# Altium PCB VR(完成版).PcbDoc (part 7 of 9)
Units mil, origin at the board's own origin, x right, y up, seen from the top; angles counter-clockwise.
Board outline 2839.68 x 2020.7 mil, 6 copper layers (TOP, GND02, SIN03, SIN04, PWR05, BOTTOM); 494 components, 404 nets, 7124 pads, 1123 vias.
Unrouted connection lines stored in the file: 10.
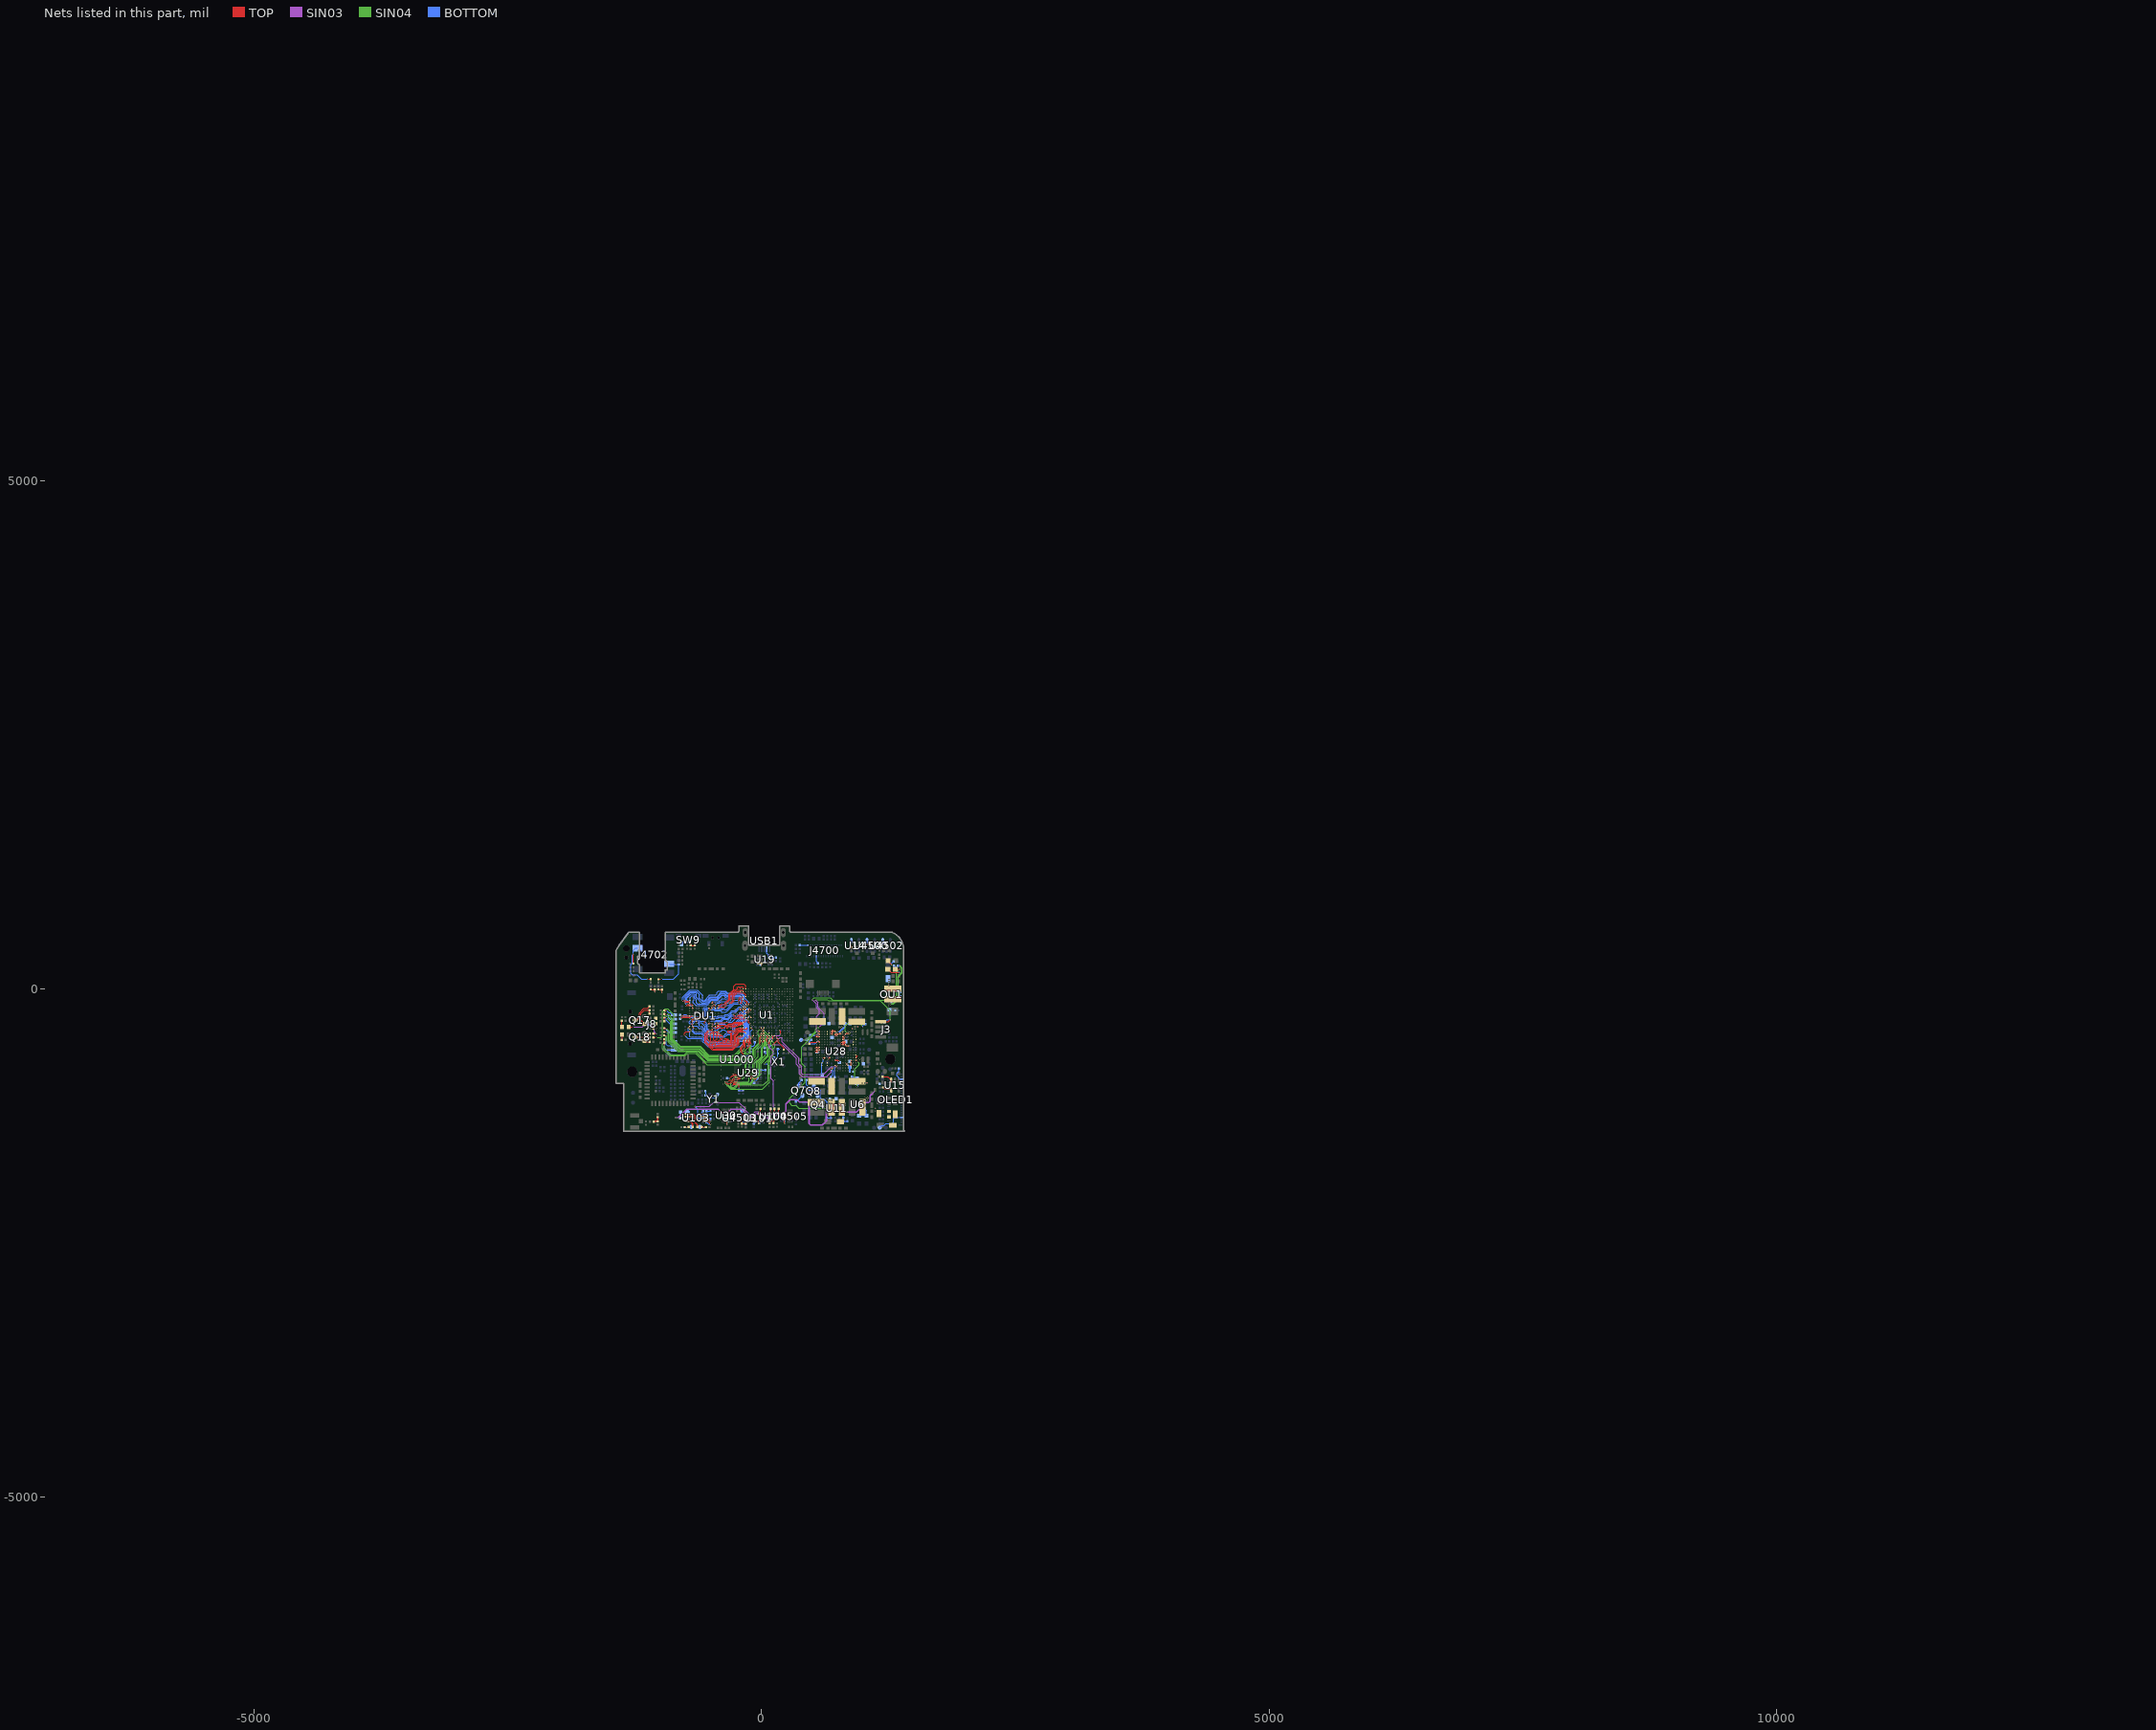
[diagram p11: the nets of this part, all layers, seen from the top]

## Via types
v1: diameter 14, hole 8, TOP to BOTTOM, tented both sides, 707 vias
v2: diameter 16, hole 10, TOP to BOTTOM, tented both sides, 275 vias
v3: diameter 16, hole 8, TOP to BOTTOM, tented both sides, 134 vias
v4: diameter 8, hole 8, TOP to BOTTOM, tented both sides, 3 vias
v5: diameter 10, hole 10, TOP to BOTTOM, tented both sides, 2 vias
v6: diameter 14, hole 8, TOP to BOTTOM, tented top, 1 vias
v7: diameter 14, hole 10, TOP to BOTTOM, tented both sides, 1 vias

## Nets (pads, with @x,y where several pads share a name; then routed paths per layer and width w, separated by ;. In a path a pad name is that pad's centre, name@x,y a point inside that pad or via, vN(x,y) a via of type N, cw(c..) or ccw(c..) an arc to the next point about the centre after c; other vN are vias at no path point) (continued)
N17861480: C240.1 R186.2 Y1.1 | length 203.2
  BOTTOM w5: C240.1@-551,-1006 -547.62,-1009.38 R186.2@-547.62,-1048.69 -522.31,-1074 -440,-1074 -430.01,-1064.01 Y1.1@-430.01,-1037.17
N20258136: D3.1 R18.1 | length 94.7
  TOP w5: D3.1@1246.33,276.14 v1(1283.73,238.74) v1@1283.73,238.14
  BOTTOM w5: v1(1283.73,238.74) 1283.73,251.71 R18.1@1303.73,271.71
N20498419: C8.1 U1.Y15 | length 140.8
  TOP w5: U1.Y15@153.54,-486.23 166,-498.69 166,-524 222,-580 C8.1@222,-598.64
N20508570: C31.2 R5.1 X1.3 | length 154
  BOTTOM w5: X1.3@117.7,-681.86 151.33,-681.86 162.19,-671 C31.2@162.19,-634.86 ; C31.2@163,-634.86 R5.1@163,-593 v1(190,-593)
N21025268: DR5.1 U1.T5 | length 279.4
  TOP w4: U1.T5@-102.36,-383.86 v1(-89.56,-396.65)
  BOTTOM w5: v1@-88.69,-397.63 -107.08,-416.02 -107.08,-503.08 -121,-517 -121,-552 -108,-565 -78,-565 -63.98,-550.98 DR5.1@-63.98,-525.69
N21042222: C134.2 R88.2 R89.1 | length 83.1
  BOTTOM w5: R88.2@766.81,-1305.24 R88.2@766.81,-1303.69
  BOTTOM w10: R88.2@766.81,-1303.69 C134.2@848.41,-1303.69
N21042253: D12.1 L9.2 U11.1
  other v2: 766.73,-1150.86 825.73,-1146.86 767.73,-1127.86 825.73,-1126.86
N21042265: R85.1 R89.2 U11.3 | length 510.1
  SIN03 w15: v1(844,-1213) 936,-1213 1028,-1121 1054,-1121 1070,-1105 1070,-1054.59 v2(1119.73,-1004.86) v2(1119.73,-984.86)
  BOTTOM w5: U11.3@803.25,-1212.26 U11.3@807.61,-1212.26
  BOTTOM w10: R89.2@807.61,-1269.86 U11.3@807.61,-1212.26 ; v1@843.26,-1212.26 v1(844,-1213)
  BOTTOM w15: U11.3@807.61,-1212.26 v1@843.26,-1212.26
N21069307: D37.1 R136.1 R140.2 USB1.4 | length 160.2
  BOTTOM w5: USB1.4@54.32,391.45 54.32,353 70.73,336.59 R140.2@70.73,309.27 ; R140.2@70.73,309.14 R140.2@70.73,309.27 ; R136.1@141.73,309.14 70.86,309.14 R140.2@70.73,309.27
N21069496: R137.2 U19.3 | length 41.8
  TOP w5: U19.3@-11.45,250.74 6.13,250.74 7.73,249.14 v1@7.73,227.14
  other v1: 7.73,233.14
N21107518: C176.2 D14.1 J8.4 R121.2
  other v1: -1029.27,-398.86 -1030.27,-378.86
N21149587: OU1.3 R22.2 R23.1 | length 119.9
  BOTTOM w5: OU1.3@1318.13,3.35 1318.13,-26.26 1324.11,-32.24 R22.2@1365.73,-32.24 R23.1@1365.73,-72.48
N21149589: OD1.1 OL1.2 OU1.1
  other v1: 1256,34.14 1256,55.14 1256,74 1257,93.14
N21179643: C206.1 C208.1 C212.2 R152.2 U28.C3 U28.D3 U28.E3 | length 145.8
  TOP w10: U28.E3@879.36,-702.6 v3(892.16,-715.4) U28.D3@879.36,-728.19 v3(892.16,-740.98)
  TOP w12: U28.C3@879.36,-753.78 v3(892.16,-740.98)
  BOTTOM w5: 903.24,-854.03 R152.2@890.41,-866.86 893.41,-869.86 935.45,-869.86 C212.2@941.84,-876.25
N21179651: C206.2 C208.2 U28.C4 | length 107.9
  TOP w5: v3(840.98,-740.99) U28.C4@853.77,-753.78
  BOTTOM w5: v3(840.98,-740.99) v3@843.54,-740.99 ; C206.2@870.96,-773.31 C206.2@873.41,-770.86
  BOTTOM w15: v3@843.54,-740.99 C206.2@873.41,-770.86 ; C208.2@870.96,-814.86 C206.2@870.96,-773.31
N21179685: C212.1 U28.E1 | length 334.8
  TOP w5: U28.E1@930.54,-702.6 v3(943.34,-715.4)
  SIN04 w8: v2(941.73,-963.86) 941.73,-933.73 919,-911 919,-791 963,-747 963,-735.06 v3(943.34,-715.4)
  BOTTOM w15: v2@941.84,-963.86 C212.1@941.84,-931.37
N21180774: C202.1 U28.F1 U28.G1 | length 54.3
  TOP w8: U28.G1@930.54,-651.42 943.34,-664.22 U28.F1@930.54,-677.01 v3(943.34,-689.81)
  other v3: 968.93,-689.81
N21184464: Q4.3 U28.T15 | length 1281.7
  TOP w5: v3(559.48,-408.31) U28.T15@572.27,-421.1
  SIN04 w4: v3(559.48,-408.31) 396,-571.78 396,-732 432,-768 432,-923 278,-1077 278,-1126 300,-1148 340,-1148 368,-1176 622.26,-1176 v2(629,-1169.26)
  BOTTOM w5: Q4.3@603.96,-1169.26 v2(629,-1169.26)
N21200318: C235.1 C249.1 R318.2 | length 79.2
  TOP w5: R318.2@-1060.89,-1305.86 cw(c-1056.07,-1310.69) R318.2@-1056.07,-1303.86
  TOP w15: R318.2@-1056.07,-1303.86 C249.1@-1021.27,-1303.86 C235.1@-1021.27,-1264.86
N21221879: L11.1 U28.K15 U28.K16 | length 36.2
  TOP w12: v3(533.89,-587.44) U28.K16@546.68,-574.65 ; v3(559.48,-587.44) U28.K15@572.27,-574.65
  other v1: 551.73,-1093 579.73,-1092 528,-1090 503,-1089
N21222303: R19.1 U28.R5 | length 391.2
  TOP w5: U28.R5@828.18,-446.69 840.98,-433.89 v3(866.56,-433.89)
  SIN04 w4: v3(866.56,-433.89) 842.89,-433.89 826,-417 826,-364 855,-335 964,-335 990,-361 v1(990,-375)
  BOTTOM w5: v1(990,-375) 1016.76,-348.24 R19.1@1022.41,-348.24 R19.1@1024.33,-350.15
N21222388: D1.2 U28.R15 | length 1579.8
  TOP w5: v3(559.48,-433.89) U28.R15@572.27,-446.69 ; D1.2@1320.13,195.14 v1(1361.73,195.14)
  SIN03 w4: v1(502,-106) 545,-149 545,-188 572,-215 572,-242 545,-269 545,-419.42 v3(559.48,-433.89)
  SIN04 w4: v1(502,-106) 521,-87 681,-87 704,-110 1304,-110 1331,-83 1331,164.41 v1@1360,193.41
N21222390: D1.1 R11.2 | length 216.7
  TOP w5: D1.1@1245.33,192.54 D1.1@1245.33,195.14 1276.33,164.14 v1(1359.73,164.14)
  BOTTOM w5: R11.2@1307.04,229.14 1333.73,202.45 1333.73,190.14 v1(1359.73,164.14)
N21223043: C67.1 R12.1 U28.M15 | length 161.4
  TOP w5: v3(559.48,-510.67) U28.M15@572.27,-523.46
  BOTTOM w5: R12.1@489.87,-504.24 R12.1@490.41,-504.24 473.44,-521.22 C67.1@473.44,-540.48 473.44,-541.24 528.9,-541.24 v3(559.48,-510.67)
N21226147: D2.1 R17.1 SW9.1 | length 163.1
  TOP w5: v1(-695.27,458.14) -694.27,457.14 R17.1@-694.27,429.52
  TOP w10: R17.1@-694.27,429.52 -692.72,427.97 D2.1@-656.27,427.97
  BOTTOM w5: SW9.1@-785.71,446.06 -773.62,458.14 v1(-695.27,458.14)
N21229926: L1.1 U28.L5 | length 43.7
  TOP w12: U28.L5@828.18,-549.05 v3(840.98,-561.85) v3(866.57,-561.84)
  other v2: 993,-927 1016,-927 1039.73,-926.86
N21230780: L2.1 U28.R12 U28.T12
N21231924: L3.1 U28.R8 U28.R9 | length 72.4
  TOP w10: U28.R9@725.82,-446.69 v3(738.62,-433.89)
  TOP w12: U28.R9@725.82,-446.69 v3@738.62,-459.48 ; v3@738.62,-459.48 U28.R8@751.41,-446.69 v3(738.62,-433.89)
  other v3: 738.73,-458.86 789.8,-433.9 773,-394 790,-378 767,-377
N21232804: L5.1 U28.N6 U28.P6 | length 54.3
  TOP w12: U28.N6@802.59,-497.87 v3(815.39,-485.07) U28.P6@802.59,-472.28 v3(815.39,-459.48)
  other v3: 923,-393 898,-392 923,-372 948,-372
N21233677: R14.1 U28.M16 | length 80.3
  TOP w5: R14.1@473.44,-540.48 490.45,-523.46 U28.M16@546.68,-523.46
N21233685: L6.1 U28.C14 U28.D14
N21233778: L7.1 U28.C12 U28.D12
N21360092: C95.2 C96.2 U29.K2 | length 103.5
  TOP w5: v1(-221.22,-972.78) U29.K2@-221.22,-936.13
  BOTTOM w5: v1(-221.22,-972.78) -220.6,-973.4 C96.2@-220.6,-1000.41 C95.2@-181.64,-1000.41
N21360138: R326.2 U29.H6 | length 87.9
  TOP w5: v1(-308,-877.63) -287.76,-857.39 U29.H6@-260.59,-857.39
  BOTTOM w5: R326.2@-340,-878 -339.63,-877.63 v1(-308,-877.63)
N21360140: R325.2 U29.T5 | length 63.1
  TOP w5: v1(-103.11,-897.89) U29.T5@-103.11,-877.07
  BOTTOM w5: v1(-103.11,-897.89) -97.8,-897.89 R325.2@-71.69,-924
N21487734: R28.2 U1.AA12 | length 106.1
  TOP w5: v1(63.98,-550.21) 83,-531.2 83,-518.05 U1.AA12@76.77,-511.82
  BOTTOM w5: R28.2@32.75,-584.48 32.75,-564.25 46.79,-550.21 v1(63.98,-550.21)
N21487790: R125.1 U1.AA4 | length 95.7
  TOP w5: v1(-139,-560) -126,-547 -126,-513.77 U1.AA4@-127.95,-511.82
  BOTTOM w5: v1(-139,-560) -129.12,-569.88 -123.12,-569.88 R125.1@-108,-585
N21569694: U28.T6
N21839117: Q7.3 Q8.1 R92.1 | length 322.2
  BOTTOM w5: R92.1@399.41,-896.24 367.41,-928.24 Q7.3@367.41,-958.86 426.73,-958.86 466.73,-998.86 540.73,-998.86 553.91,-1012.04 Q8.1@553.91,-1049.86
N21839131: C136.2 Q8.3 R90.2 R91.2 U11.4 | length 578.8
  BOTTOM w5: R90.2@445.41,-895.86 445.41,-945.54 459.73,-959.86 Q8.3@516.41,-959.86 540.55,-984 564,-984 583,-1003 583,-1070 598.86,-1085.86 617.86,-1085.86 646,-1114 646,-1179 679.26,-1212.26 U11.4@683.18,-1212.26 ; C136.2@683.18,-1271.41 C136.2@685.21,-1271.41 C136.2@685.21,-1269.86
  BOTTOM w10: R91.2@644.41,-1269.86 C136.2@685.21,-1269.86 ; C136.2@683.18,-1271.41 U11.4@683.18,-1212.26
N22015419: C51.1 D6.1 L4.2 U6.1
  other v2: 1123.73,-1203.86 1123.73,-1174.86 1019,-1101 1043.73,-1099.86 1018.73,-1074.86 1044.73,-1074.86
N22015421: C51.2 D5.2 D13.1
N22015458: R9.1 R10.2 U6.3 | length 166.9
  BOTTOM w5: U6.3@998.59,-1176.26 U6.3@1013.13,-1176.26
  BOTTOM w10: R9.1@962.41,-1247.86 R10.2@1034.41,-1247.86 1034.41,-1197.54 U6.3@1013.13,-1176.26
N22028290: Q18.3 R475.2 | length 156.7
  TOP w5: Q18.3@-1242.27,-474.36 -1135.8,-474.36 R475.2@-1100.3,-438.86
N22028293: Q17.3 R476.2 | length 223.3
  TOP w5: Q17.3@-1242.27,-308.36 -1230.36,-308.36 -1202,-280 -1202,-238 -1157,-193 -1121.84,-193 R476.2@-1100.3,-171.46
N22028410: Q17.1 R477.2 R478.2 | length 256.1
  TOP w5: Q17.1@-1152.27,-345.86 -1187,-311.13 -1187,-242 -1152.86,-207.86 R477.2@-1100.3,-207.86 R478.2@-1100.3,-244.86
N22029251: Q18.1 R479.1 R480.1 | length 97.6
  TOP w5: Q18.1@-1152.27,-511.86 -1142.27,-521.86 R480.1@-1100.3,-521.86 R479.1@-1100.3,-480.36
N22327296: C4509.1 U4502.4 | length 81
  TOP w5: C4509.1@1162.73,411.59 1191.78,440.64 v1(1195.23,440.64)
  BOTTOM w5: v1(1195.23,440.64) U4502.4@1195.23,477.14
N22327327: C4506.1 U4500.4 | length 107.2
  TOP w5: C4506.1@996.73,406.59 996.73,428.14 1009.23,440.64 v1(1040.73,440.64)
  BOTTOM w5: v1(1040.73,440.64) U4500.4@1040.73,477.14
N22327471: C204.1 U14.4 | length 70.2
  TOP w5: v1(886.23,440.64) 886.73,440.14 C204.1@886.73,407.14
  BOTTOM w5: v1(886.23,440.64) U14.4@886.23,477.14
N22328046: OLED1.5 T35.1 | length 280.7
  BOTTOM w5: T35.1@1165.73,-1366.86 1185.73,-1346.86 1207.73,-1346.86 1228.73,-1325.86 1285.73,-1325.86 1300.73,-1310.86 1300.73,-1277.86 1312.56,-1266.02 v2(1357.73,-1266.02) OLED1.5@1385.29,-1266.02
N22328103: OLED1.37 R138.2 | length 144.4
  BOTTOM w5: R138.2@1351.73,-785.86 1351.73,-812.86 1332.73,-831.86 1332.73,-856.86 1363.94,-888.07 OLED1.37@1385.29,-888.07
N22332510: C217.1 U15.4 | length 93.7
  TOP w5: C217.1@1198.18,-969.53 1198.18,-970.31 1215.87,-988 1268.37,-988 U15.4@1279.23,-998.86
N22332561: R127.2 U15.3 | length 98.3
  TOP w5: R127.2@1194.73,-865.61 1245.98,-865.61 U15.3@1279.23,-898.86
N22348396: R1006.2 R1007.1 U1000.1 | length 95
  BOTTOM w5: U1000.1@-181.16,-657.6 -180.81,-657.25 R1007.1@-122.27,-657.25 R1006.2@-122.27,-693.25
N22356402: U1.C13
N22386017: R484.2 R485.1 U100.1 | length 71.7
  TOP w5: U100.1@90.02,-1224.33 v2(90.02,-1204.86) 90.02,-1182.57 R485.1@92.73,-1179.86
  BOTTOM w5: v2(90.02,-1204.86) 90.02,-1182.57 R484.2@92.73,-1179.86
N22386115: R486.2 U101.12 | length 54
  TOP w5: U101.12@-27.27,-1225.55 -27.27,-1221.27 -7.27,-1201.27 R486.2@-7.27,-1179.86
N22386164: C189.2 R488.1 R489.1 U4503.C2 | length 131.4
  TOP w5: U4503.C2@-213.27,-1284.86 -192.27,-1305.86 C189.2@-192.27,-1326.41 -190.35,-1324.48 R488.1@-155.27,-1324.48
  BOTTOM w5: v2(-191.27,-1306.72) -173.03,-1306.72 R489.1@-155.27,-1324.48
N22386171: TST.1 U4503.A3 | length 59.3
  TOP w5: U4503.A3@-197.47,-1253.36 -188.27,-1244.16 v2(-188.27,-1231.86)
  BOTTOM w5: v2(-188.27,-1231.86) TST.1@-188.27,-1197.86
N22386468: R483.1 U100.5 | length 50
  TOP w5: R483.1@82.73,-1322.86 110.89,-1294.7 U100.5@110.89,-1284.57
N22386474: R482.1 U100.6 | length 42.4
  TOP w5: R482.1@120.73,-1322.86 120.73,-1306.7 130.57,-1296.86 U100.6@130.57,-1284.57
N22386496: R126.2 U100.11 | length 43.4
  TOP w5: U100.11@130.57,-1223.15 130.57,-1180.02 R126.2@130.73,-1179.86
N22386590: R487.2 U101.4 | length 69.7
  TOP w5: U101.4@-74.58,-1292.54 -55.59,-1292.54 v2(-45.27,-1302.86)
  BOTTOM w5: R487.2@-72.27,-1324.86 -67.27,-1324.86 v2(-45.27,-1302.86)
N22386600: R128.1 U101.6 | length 60.1
  TOP w5: U101.6@-27.27,-1320.16 v2(-27.27,-1291.86)
  BOTTOM w5: v2(-27.27,-1291.86) -15.65,-1303.48 R128.1@-15.65,-1318.86
N22386644: R481.1 U100.10 | length 51.6
  TOP w5: U100.10@151.44,-1224.33 168.73,-1207.04 R481.1@168.73,-1179.86
N22386973: C292.1 U30.10 | length 56.2
  TOP w5: v2(-337.4,-1333.73) U30.10@-337.4,-1307.92
  BOTTOM w5: v2(-337.4,-1333.73) -337.4,-1313.44 C292.1@-330.27,-1306.31
N22437552: C328.2 R506.2 | length 39
  BOTTOM w5: C328.2@-503.03,-1239.08 C328.2@-501.03,-1241.08
  BOTTOM w8: R506.2@-539.2,-1239.08 C328.2@-503.03,-1239.08
N22437762: C329.1 ED2.1 R5122.1 TP69.1 | length 112.1
  TOP w5: R5122.1@-592.89,-1358.86 R5122.1@-590.89,-1360.86
  TOP w15: R5122.1@-590.89,-1360.86 C329.1@-544.72,-1360.86
  BOTTOM w5: ED2.1@-547.05,-1359.08 ED2.1@-544.27,-1361.86
  BOTTOM w15: TP69.1@-606.2,-1359.08 v2(-568.27,-1359.08) ED2.1@-547.05,-1359.08
N22437782: C331.1 ED1.1 R5121.1 TP68.1 | length 107.4
  TOP w5: C331.1@-754.82,-1360.86 C331.1@-753.82,-1359.86
  TOP w15: C331.1@-753.82,-1359.86 v2(-735.27,-1359.86) R5121.1@-713.65,-1359.86
  BOTTOM w5: ED1.1@-754.27,-1360.86 ED1.1@-752.5,-1359.08
  BOTTOM w15: ED1.1@-752.5,-1359.08 TP68.1@-689.2,-1359.08
N22437840: C332.1 FB3.2 U103.6 | length 58.6
  TOP w15: U103.6@-732.85,-1258.06 v2@-674.27,-1258.06
  other v2: -692.27,-1258.06 -674.27,-1257.86
N22437866: R507.1 U103.4 | length 96.9
  TOP w5: v2(-607.27,-1232.47) U103.4@-555.69,-1232.47
  BOTTOM w5: v2(-607.27,-1232.47) v2@-604.96,-1232.47
  BOTTOM w8: v2@-604.96,-1232.47 R507.1@-574.58,-1202.08
N22437896: C327.2 U103.2 | length 88.7
  TOP w5: U103.2@-555.69,-1283.65 -521.23,-1283.65 v2(-500.65,-1304.24)
  BOTTOM w5: v2(-500.65,-1304.24) C327.2@-500.65,-1279.08
N22437902: R5122.2 U103.5 | length 207.4
  TOP w15: U103.5@-732.85,-1232.47 -668.53,-1232.47 -653,-1248 -653,-1315 -628.27,-1339.73 R5122.2@-628.27,-1358.86
N22437906: R506.1 U103.3 | length 93.7
  TOP w5: v2(-608.07,-1253.06) -560.69,-1253.06 U103.3@-555.69,-1258.06
  BOTTOM w8: v2(-608.07,-1253.06) -588.55,-1253.06 R506.1@-574.58,-1239.08
N22437933: C330.2 R507.2 | length 38.2
  BOTTOM w8: R507.2@-539.2,-1202.08 C330.2@-501.03,-1202.08
N22437977: R5121.2 U103.8 | length 95
  TOP w15: U103.8@-732.85,-1309.24 -695.76,-1309.24 -678.27,-1326.73 R5121.2@-678.27,-1359.86
N22440849: D29.1 FB1.2 J4702.6 | length 416.8
  TOP w8: FB1.2@-1015.27,95.43 v1(-983.56,95.43)
  BOTTOM w8: v1(-983.56,95.43) -864.57,95.43 -812.1,147.9 -812.1,242.14 v1(-842.27,242.14) -902.85,242.14 J4702.6@-907.76,247.05
N22440857: D27.1 FB2.2 J4702.4 | length 599.8
  TOP w8: D27.1@-1260.44,249.14 v1(-1260.44,342.97) ; v1(-1119.64,95.77) FB2.2@-1088.63,95.77
  BOTTOM w8: J4702.4@-1218.78,400.59 -1237.41,400.59 -1260.44,377.56 v1(-1260.44,342.97) -1270,333.41 -1270,253 -1285,238 -1285,153 -1271,139 -1223,139 -1179.77,95.77 v1(-1119.64,95.77)
N22440958: C211.1 R151.2 | length 63.3
  TOP w10: C211.1@-1014.94,-6.31 -979.82,-6.31 R151.2@-978.27,-7.86 v1(-978.27,-33.86)
N22440960: C209.1 R150.2 | length 62.6
  TOP w10: C209.1@-1088.27,-6.31 -1053.15,-6.31 R150.2@-1051.61,-7.86 -1051.61,-22.86 v1(-1051.61,-33.19)
N22449236: D39.1 R5124.2 | length 53.6
  TOP w5: R5124.2@-1372.65,-502.86 R5124.2@-1371.27,-501.48
  TOP w8: R5124.2@-1371.27,-501.48 D39.1@-1371.27,-449.86
N22449247: D40.1 R1010.2 | length 60
  TOP w5: R1010.2@-1372.74,-314.94 R1010.2@-1372.65,-314.86
  TOP w8: D40.1@-1372.74,-374.86 R1010.2@-1372.74,-314.94
N22507754: J4700.2 R5117.2 | length 82.2
  BOTTOM w5: R5117.2@376.11,430.98 376.27,431.14 J4700.2@458.26,431.14
N22507764: J4700.9 R5118.2 | length 79
  BOTTOM w5: J4700.9@540.94,322.48 540.94,269.78 R5118.2@559.53,251.19
N22528851: R5132.2 U4505.4 | length 79.5
  TOP w5: U4505.4@221.69,-1283.39 229.73,-1283.39 v2(229.73,-1326.86)
  BOTTOM w5: v2(229.73,-1326.86) R5132.2@229.73,-1298.86
N22528855: R5133.2 U4505.9 | length 83.4
  TOP w5: v2(306.73,-1248.86) 321.57,-1263.7 U4505.9@341.77,-1263.7
  BOTTOM w5: v2(306.73,-1248.86) 327.73,-1248.86 R5133.2@342.73,-1263.86
N22528886: R5134.2 U4505.3 | length 61.4
  TOP w5: U4505.3@221.69,-1263.7 254.89,-1263.7 v2(255.73,-1262.86)
  BOTTOM w5: R5134.2@228.73,-1262.86 v2(255.73,-1262.86)
N22528888: R5135.2 U4505.2 | length 93.1
  TOP w5: U4505.2@221.69,-1244.02 240.57,-1244.02 247.73,-1236.86 v2(268.73,-1236.86)
  BOTTOM w5: R5135.2@229.73,-1226.86 239.73,-1236.86 v2(268.73,-1236.86)
N218456171: Q7.1 R93.2 | length 88.9
  BOTTOM w5: R93.2@340.41,-1107.86 345.91,-1107.86 Q7.1@404.91,-1048.86
NALE: U1.V12
NCE0: U1.Y12
NCE1: U1.W12
NCE2: U1.Y9
NCE3: U1.AA9
NCLE: U1.AA13
NDQ0: U1.T10 U29.H3 | length 1245.4
  TOP w4: v1(12.79,-396.65) U1.T10@25.59,-383.86
  TOP w5: v1(-355,-919) -337,-937 -317,-937 -296.44,-916.44 U29.H3@-260.59,-916.44 -283.44,-916.44
  SIN04 w4: v1(-355,-919) -355,-933 -301,-987 10,-987 82,-915 82,-720 102,-700 102,-670 121,-651 121,-586 135,-572 135,-543 90.92,-498.92 90.92,-474.77 v1(12.79,-396.65)
NDQ1: U1.U10 U29.H4 | length 1100.9
  TOP w4: v1(12.79,-422.24) U1.U10@25.59,-409.45
  TOP w5: v1(-332,-919) -309.76,-896.76 U29.H4@-260.59,-896.76
  SIN04 w4: v1(-332,-919) -332,-941 -296,-977 -259,-977 -229,-947 19,-947 65,-901 65,-720 91,-694 91,-665 109,-647 109,-563 94,-548 94,-522 77.28,-505.27 77.28,-486.73 v1(12.79,-422.24)
NDQ2: U1.V10 U29.H5 | length 923.6
  TOP w4: v1(12.79,-447.83) U1.V10@25.59,-435.04
  TOP w5: v1(-283.44,-877.07) U29.H5@-260.59,-877.07
  SIN04 w4: v1(-283.44,-877.07) -283.44,-897 -301,-914.56 -301,-958 -291,-968 -266,-968 -234,-936 -104,-936 -78,-910 -78,-887 -64,-873 -55,-873 -18,-836 -18,-735 59,-658 59,-591 43,-575 43,-478.04 v1(12.79,-447.83)
NDQ3: U1.W10 U29.J2 | length 782.7
  TOP w4: v1(12.79,-473.42) U1.W10@25.59,-460.63
  TOP w5: v1(-284,-955) -271,-942 -246.78,-942 U29.J2@-240.91,-936.13
  SIN04 w4: v1(-284,-955) -256,-927 -108,-927 -87,-906 -87,-859 -60.14,-832.14 -53.14,-832.14 -44,-823 -44,-725 11,-670 11,-585 35,-561 35,-495.63 v1(12.79,-473.42)
NDQ4: U1.Y10 U29.J3 | length 715.8
  TOP w4: v1(12.79,-499.02) U1.Y10@25.59,-486.23
  TOP w5: v1@-285,-932 -256.47,-932 U29.J3@-240.91,-916.44
  SIN04 w4: v1(-284.32,-931.32) -268,-915 -130,-915 -120,-905 -120,-875 -85,-840 -85,-819 -67,-801 -67,-735 0,-668 0,-581 26,-555 26,-512.23 v1(12.79,-499.02)
NDQ5: U1.AA10 U29.J4 | length 542.9
  TOP w4: v1(12.79,-524.61) U1.AA10@25.59,-511.82
  TOP w5: U29.J4@-240.91,-896.76 -226.15,-882 v1@-201,-882
  SIN04 w4: v1@-201,-882 -182,-882 -147.08,-847.08 -110.08,-847.08 -95,-832 -95,-814 -85.5,-804.5 -85.5,-724.5 -30,-669 -30,-593 12.79,-550.21 v1(12.79,-524.61)
  other v1: -201,-884
NDQ6: U1.T9 U29.J5 | length 613
  TOP w4: v1(-12.8,-396.65) U1.T9@0,-383.86
  TOP w5: U29.J5@-240.91,-877.07 -233.84,-870 -211,-870 v1@-201,-860
  SIN04 w4: v1@-201,-860 -161,-820 -161,-735 -85,-659 -85,-591 -23,-529 -23,-464 -31,-456 -31,-414.86 v1(-12.8,-396.65)
  other v1: -202,-858
NDQ7: U1.V9 U29.J6 | length 668.1
  TOP w4: v1(-12.8,-447.83) U1.V9@0,-435.04
  TOP w5: v1(-283,-842) -256.3,-842 U29.J6@-240.91,-857.39
  SIN04 w4: v1(-283,-842) -254,-871 -190,-871 -148,-829 -148,-737 -74,-663 -74,-592 -12.8,-530.8 v1(-12.8,-447.83)
NDQS: U1.W9 U29.U5 | length 477.1
  TOP w5: v1(-115,-826) -115,-845.5 U29.U5@-83.43,-877.07 ; v1(-12.8,-550.21) -12.8,-473.43 U1.W9@0,-460.63
  SIN04 w4: v1(-115,-826) -115,-721 -62,-668 -62,-599.42 v1(-12.8,-550.21)
NRB0: R26.2 R27.2 R29.2 U1.W11 U29.W5 | length 664.7
  TOP w5: v1(-64,-897) -64,-886 -55.07,-877.07 U29.W5@-44.06,-877.07 ; U1.W11@51.18,-460.63 63.98,-473.43 v1(63.98,-499.02)
  SIN04 w4: v1(-64,-897) -5,-838 -5,-737 69,-663 69,-576 51,-558 51,-512 v1(63.98,-499.02)
  BOTTOM w5: v1(-64,-897) -45,-897 -36.64,-888.64 R29.2@-36.64,-874.86 R27.2@-36.64,-836.91 R26.2@-36.64,-798.97
NRB1: R24.2 R25.1 U1.Y11 | length 412.8
  TOP w5: U1.Y11@51.18,-486.23 47,-490.41 47,-507.65 v1(63.98,-524.62)
  SIN04 w4: v1(31,-737) 80,-688 80,-540.65 v1(63.98,-524.62)
  BOTTOM w5: v1(31,-737) 53,-737 72.38,-756.38 R25.1@72.38,-797 71.69,-797.69 R24.2@71.69,-833
NRBX: R25.2 R26.1 | length 39.1
  BOTTOM w5: R26.1@-1.26,-798.97 0.7,-797 R25.2@37,-797
NRE: R28.1 U29.W6 | length 306.2
  TOP w5: v1(-62.39,-857.39) U29.W6@-44.06,-857.39
  SIN04 w4: v1(-62.39,-857.39) -30,-825 -30,-726 v1(46,-650)
  BOTTOM w5: R28.1@32.75,-619.86 46,-633.11 v1(46,-650)
NWE: U1.Y13
PA-SHDN: R5120.2 R5123.2 U1.U16 | length 2026.3
  TOP w5: U1.U16@179.13,-409.45 191.93,-422.24 v1(191.93,-447.83)
  SIN03 w4: v2(-655,-1159) -511,-1159 -470,-1118 -220,-1118 -161,-1177 -161,-1194 -117,-1238 -88,-1238 -61,-1211 -32,-1211 -14,-1229 26,-1229 56,-1259 87,-1259 96.53,-1249.47 96.53,-1240.47 132,-1205 132,-1172 120,-1160 120,-909 94,-883 94,-664 120,-638 120,-617 77,-574 77,-505 124,-458 181.76,-458 v1(191.93,-447.83)
  BOTTOM w5: v2(-655,-1159) -626,-1188 -626,-1264.28 R5123.2@-612.2,-1278.08 ; R5123.2@-612.2,-1280.2 R5123.2@-612.2,-1278.08 ; R5120.2@-574.58,-1276.08 -610.2,-1276.08 R5123.2@-612.2,-1278.08
PHONE_DET: R5119.1 R5120.1 U103.1 | length 145.7
  TOP w5: U103.1@-555.69,-1309.24 -522.89,-1309.24 v2(-501.27,-1330.86)
  BOTTOM w5: R5120.1@-539.2,-1276.08 R5119.1@-539.2,-1313.08 -521.42,-1330.86 v2(-501.27,-1330.86)
PMU-SCK: R473.2 U1.AA15 U28.B10 | length 978.3
  TOP w5: v1(115.16,-550.2) U1.AA15@153.54,-511.82 ; v3(687.44,-792.17) U28.B10@700.23,-779.37
  SIN03 w4: v1(115.16,-550.2) 209.21,-550.2 343,-684 343,-744 374,-775 374,-835 402,-863 641,-863 687.44,-816.56 v3(687.44,-792.17)
  BOTTOM w5: R473.2@686.75,-866.86 705.73,-847.88 705.73,-810.46 v3(687.44,-792.17)
PMU-SDA: R474.2 U1.W14 U28.C9 | length 1025.8
  TOP w4: U1.W14@127.95,-460.63 v1(140.75,-473.43)
  TOP w5: U28.C9@725.82,-753.78 v3(738.62,-766.58)
  SIN03 w4: v1(140.75,-473.43) 156.32,-489 175,-489 187,-477 201,-477 206,-482 206,-520 367.5,-681.5 367.5,-737.5 397,-767 397,-830 408,-841 615,-841 689.42,-766.58 v3(738.62,-766.58)
  BOTTOM w5: R474.2@723.08,-866.86 723.08,-782.11 v3(738.62,-766.58)
PS: C50.1 C57.1 C61.1 C64.1 C66.1 C68.1 C71.2 C72.1 C91.2 C92.2 C130.2 C131.2 C263.2 C270.2 C333.1 FB3.1 L9.1 OL1.1 OU1.5 Q4.4 Q4.7 R11.1 U11.6 U28.E9 U28.F11 U28.F13 U28.H16 U28.J15 U28.J16 U28.L6 U28.M5 U28.M6 U28.P15 U28.P16 U28.R7 U28.R10 U28.T9 U28.T10 | length 3412.6
  TOP w11.81: v3(533.89,-459.49) U28.P16@546.68,-472.28 v3(559.48,-459.49) U28.P15@572.27,-472.28 ; v3@559.48,-613.03 U28.J16@546.68,-600.24 v3(533.89,-613.03) U28.H16@546.68,-625.83 559.48,-613.03 U28.J15@572.27,-600.24 ; v3(610.66,-689.81) U28.F13@623.45,-677.01 ; v3(661.84,-689.81) U28.F11@674.63,-677.01 ; v3(687.44,-408.31) U28.T10@700.23,-421.1 ; U28.R10@700.23,-446.69 v3(687.44,-433.89) v3(713.03,-408.31) U28.T9@725.82,-421.1 ; U28.E9@725.82,-702.6 751.42,-702.6 v3(764.22,-715.4) ; v3(764.21,-433.89) U28.R7@777,-446.69 ; U28.M6@802.59,-523.46 803.46,-523.46 815.82,-535.82 ; U28.M6@802.59,-523.46 v3(789.8,-536.26) U28.L6@802.59,-549.05 815.82,-535.82 ; U28.M6@802.59,-523.46 v3(815.39,-510.66) U28.M5@828.18,-523.46 815.82,-535.82
  SIN03 w15: v2(-845.27,-1270.86) v5(-824,-1270.86) -820.86,-1270.86 -734,-1184 -425,-1184 -392,-1217 -328,-1217 -295,-1184 -196,-1184 -126,-1254 -78,-1254 -54,-1230 -35,-1230 -21,-1244 17,-1244 49,-1276 115,-1276 162,-1229 218,-1229 242,-1205 242,-1133 283,-1092 353,-1092 374,-1113 446,-1113 470,-1137 470,-1327 485,-1342 601,-1342 639.73,-1303.27 v2@639.73,-1201
  SIN04 w11.81: v1@1272.67,-148 1296,-148 1344,-100 1344,117 1384,157 1384,206.87 v1(1361.73,229.14)
  BOTTOM w10: v3@533.65,-459.24 v3(533.89,-459.49) ; C68.1@600.41,-846.74 593.73,-840.06 593.73,-731.86 610.66,-714.93 v3(610.66,-689.81)
  BOTTOM w11.81: v3(764.21,-433.89) 766.21,-427.79 820.41,-373.59 C71.2@820.41,-343.24 ; C66.1@872.37,-343.24 C66.1@873.58,-342.03 ; R11.1@1342.42,229.14 v1(1361.73,229.14)
  BOTTOM w15: C263.2@487.41,-459.24 v3@533.65,-459.24 ; v3(533.89,-459.49) v3(559.48,-459.49) ; v3(764.22,-715.4) 757.4,-715.4 767.86,-725.86 C72.1@769.41,-725.86
  BOTTOM w20: C71.2@820.41,-343.24 C66.1@872.37,-343.24
  other v1: 1274,-168.86 1255.73,-168 1273.67,-149
  other v2: 641,-1219.86 641,-1201 670.73,-1124.86 692.73,-1124.86 671.73,-1098.86 693.73,-1098.86
  other v3: 559.48,-613.03
  other v4: 1257,-149
PWRON: ED25.1 J3.4 R12.2 TP61.1 | length 1706.9
  TOP w5: J3.4@1213.73,-311.11 1199.8,-325.04 J3.4@1176.25,-325.04 1237,-325.04 ; v2(1268,-305) 1247.96,-325.04 ; 1237,-325.04 1247.96,-325.04 ; 1237,-325.04 1247.96,-325.04
  SIN03 w4: v1(529,-105) 557,-133 557,-182 618,-243 618,-330 v1(569,-379)
  SIN04 w4: v1(417,-504) 446,-504 534,-416 534,-399 554,-379 v1(569,-379) ; v1(529,-105) 649,-105 662,-118 1169,-118 1268,-217 v2(1268,-305)
  BOTTOM w5: TP61.1@387.73,-514.24 397.73,-504.24 R12.2@455.03,-504.24 ; ED25.1@1213.73,-325.86 1234.59,-305 v2(1268,-305)
RED: D40.2 R475.1 | length 363.7
  TOP w5: D40.2@-1305.81,-374.86 v1(-1263.27,-374.86) ; R475.1@-1064.92,-438.86 v1(-1037.27,-438.86)
  SIN03 w4: v1(-1263.27,-374.86) -1169.86,-374.86 -1148,-353 -1084,-353 -1053,-384 -1053,-423.13 v1(-1037.27,-438.86)
RED_LED: R479.2 U1.W6 | length 1663.5
  TOP w4: v1(-89.57,-473.42) U1.W6@-76.77,-460.63
  TOP w5: R479.2@-1064.92,-480.36 v1(-1035.77,-480.36)
  SIN04 w4: v1(-1035.77,-480.36) -990.36,-480.36 -973,-463 -973,-225 -944,-196 -924,-196 -861,-259 -861,-502 -798,-565 -603.7,-565 -516.7,-652 -266,-652 -204,-590 -204,-577 -100.42,-473.42 v1(-89.57,-473.42)
REXT: R8.1 U1.W13 | length 151.2
  TOP w5: U1.W13@102.36,-460.63 115.16,-473.42 v1(115.16,-499.02)
  BOTTOM w5: R8.1@70.52,-584.48 R8.1@68,-584.48 94,-558.48 94,-520.17 v1(115.16,-499.02)
RX0_INT: U1.A13
RX-I2S-BCLK: U28.N1
RX-I2S-DIN: U28.L2
RX-I2S-LRCK: U28.M2
RX-I2S-MCLK: U28.T1
SA0: DU1.R2 U1.N4 | length 981.8
  TOP w4: v1(-752.42,-458.9) -755.42,-455.9 -755.42,-434.9 -741.08,-420.56 DU1.R2@-707.33,-420.56 ; DU1.R2@-706.91,-420.99 DU1.R2@-706.49,-420.57 ; U1.N4@-127.11,-307.09 -127.11,-329.78 v1(-113.97,-342.91)
  BOTTOM w4: v1(-752.42,-458.9) -723.47,-487.86 -584.27,-487.86 -576.27,-495.86 -576.27,-518.64 -556.01,-538.91 -527.89,-567.02 ; -525.98,-567.02 -523.48,-569.52 -210.59,-569.52 -119.01,-477.94 -119.01,-352.94 v1@-113.97,-347.91
SA1: DU1.P2 U1.M5 | length 929.7
  TOP w4: DU1.P2@-706.49,-394.98 v1(-693.69,-407.77) ; v1(-114.31,-268.7) U1.M5@-101.52,-281.5
  BOTTOM w4: v1(-693.69,-407.77) -690.34,-407.77 -659.08,-439.02 -592.01,-439.02 -556.01,-475.02 -556.01,-495.02 -556.01,-504.96 -532.01,-528.97 -517.95,-543.02 -285.89,-543.03 -256.07,-543.03 -255.01,-543.02 -214.01,-502.02 -177.01,-502.02 -139.01,-464.02 -139.01,-349.34 -155.42,-332.92 -155.42,-286.94 -148.04,-279.56 -130.64,-279.56 -130.4,-279.31 -124.92,-279.31 v1(-114.31,-268.7)
SA2: DU1.N2 U1.M4 | length 981.3
  TOP w4: v1@-721.01,-384.02 v1(-721.01,-383.02) -718.4,-380.42 -717.52,-380.42 DU1.N2@-706.49,-369.39 ; v1(-140.74,-294.3) U1.M4@-127.95,-281.5
  BOTTOM w4: v1@-721.01,-384.02 -721.01,-418.02 -704.01,-435.02 -704.01,-467.12 -696.27,-474.86 -571.27,-474.86 -566.27,-479.86 -566.27,-511.67 -544.01,-533.94 -522.92,-555.02 -290.86,-555.02 -251.1,-555.03 -247.36,-555.02 -218.03,-525.69 -218.03,-525.11 -209.83,-516.91 -198.23,-516.91 -198.17,-516.97 -172.95,-516.97 -129.01,-473.02 -129.01,-348.02 -145.01,-332.02 -145.01,-314.4 -139.9,-309.3 v1@-139.9,-294.3
SA3: DU1.N3 U1.L3 | length 891.1
  TOP w4: DU1.N3@-674.99,-369.39 v1(-662.19,-382.18) ; v1(-166.33,-268.7) U1.L3@-153.54,-255.91
  BOTTOM w4: v1(-662.19,-382.18) -674.01,-393.99 -674.01,-410.49 -657.47,-427.02 -587.04,-427.02 -544.01,-470.05 -544.01,-500 -520.01,-524 -512.98,-531.02 -280.92,-531.02 -261.04,-531.03 -259.98,-531.02 -217.98,-489.02 -181.01,-489.02 -149.01,-457.02 -149.01,-351.88 -165.42,-335.46 -165.42,-271.61 v1@-164.01,-270.19 ; v1@-165.49,-268.7 v1@-164.01,-270.19 ; v1@-164.01,-267.94 v1@-164.01,-270.19
SA4: DU1.M3 U1.K3 | length 935
  TOP w4: v1(-688.63,-356.59) DU1.M3@-675.84,-343.79 ; U1.K3@-153.54,-230.32 v1(-140.74,-243.11)
  BOTTOM w4: v1@-687.79,-356.59 -677.41,-366.96 -637.07,-366.96 -617.01,-387.02 -592.21,-387.02 -578.6,-400.64 -578.6,-411.38 -532.01,-457.97 -532.01,-495.02 -508.01,-519.02 -275.95,-519.02 -266.01,-519.03 -225.01,-478.02 -185.01,-478.02 -159.01,-452.02 -159.01,-353.19 -178.97,-333.22 -178.97,-277.71 -180.84,-275.85 -180.84,-263.32 -160.63,-243.11 v1(-140.74,-243.11) v1@-139.9,-243.11
SA5: DU1.F3 U1.J3 | length 888.6
  TOP w4: v1(-688.63,-177.45) DU1.F3@-675.84,-190.25 ; v1(-166.33,-191.93) U1.J3@-153.54,-204.73
  BOTTOM w4: v1@-687.79,-177.46 -703.08,-162.16 -703.08,-86.1 -685.87,-68.88 -668.01,-68.88 -664.01,-72.88 -664.01,-110.45 -674.42,-120.87 -674.42,-132.9 -645.8,-161.53 -537.94,-161.53 -488.32,-111.91 -431.43,-111.91 -385.54,-66.03 -368.58,-66.03 -347.58,-87.02 -219.21,-87.02 -204.01,-102.22 -204.01,-153.42 v1@-165.49,-191.93
SA6: DU1.E3 U1.H2 | length 908.9
  TOP w4: v1(-724.01,-147.02) -719.5,-151.53 -688.13,-151.53 DU1.E3@-674.99,-164.66 ; U1.H2@-179.14,-179.14 v1(-166.34,-166.34)
  BOTTOM w4: v1(-724.01,-147.02) -724.01,-117.6 -734.08,-107.53 -734.08,-93.01 -689.09,-48.02 -663.01,-48.02 -652.01,-59.02 -652.01,-94.02 -641.42,-104.61 -641.42,-136.9 -628.8,-149.53 -542.91,-149.53 -494.41,-101.02 -435.54,-101.02 -391.37,-56.85 -375.41,-56.85 -362.76,-56.84 -344.58,-75.02 -216.01,-75.02 -194.01,-97.02 -194.01,-137.83 v1@-165.49,-166.34
SA7: DU1.E2 U1.H3 | length 936.2
  TOP w4: v1(-744.01,-162.02) -741.37,-164.66 DU1.E2@-706.49,-164.66 ; U1.H3@-153.54,-179.14 v1(-140.74,-166.34)
  BOTTOM w4: v1(-744.01,-162.02) -744.01,-147.02 -739.01,-142.02 -739.01,-117.02 -744.78,-111.25 -744.78,-86.74 -694.06,-36.02 -650.01,-36.02 -641.08,-44.95 -641.08,-84.24 -587.8,-137.53 -547.88,-137.53 -527.17,-116.82 -499.38,-89.02 -437.54,-89.02 -393.37,-44.85 -380.38,-44.85 -360.5,-44.84 ; -360.49,-44.85 -342.32,-63.02 -209.01,-63.02 -184.01,-88.02 -184.01,-122.24 v1@-139.9,-166.34
SA8: DU1.D2 U1.G3 | length 947.2
  TOP w4: v1(-754.01,-137.02) -747.51,-130.53 -715.03,-130.53 DU1.D2@-706.49,-139.07 ; v1@-165.5,-115.16 -148.65,-115.16 -139.9,-123.91 -139.9,-140.75 U1.G3@-152.7,-153.55
  BOTTOM w4: v1(-754.01,-137.02) -754.01,-119 -759.01,-114 -759.01,-84 -699.03,-24.02 -637.16,-24.02 -609.01,-52.18 -609.01,-94.38 -576.6,-126.78 -564.05,-126.78 ; -564.05,-126.78 -554.11,-126.78 -504.35,-77.02 -438.54,-77.02 -394.37,-32.85 -385.35,-32.85 -355.53,-32.84 -337.35,-51.02 -203.01,-51.02 -174.01,-80.02 -174.01,-106.65 v1@-165.5,-115.16
  other v1: -166.34,-115.16
SA9: DU1.C2 U1.G4 | length 988.1
  TOP w4: v1(-775.04,-113.48) -744.08,-113.48 -737.54,-120.03 -713.03,-120.03 DU1.C2@-706.49,-113.48 ; U1.G4@-127.95,-153.55 v1(-115.15,-140.76)
  BOTTOM w4: v1@-774.01,-112.02 -774.01,-82.02 -704.01,-12.02 -632.19,-12.02 -579.8,-64.42 -579.8,-109.81 -574.08,-115.53 -559.82,-115.53 -505.66,-61.36 -450.92,-61.36 -439.08,-49.53 -439.08,-37.1 -422.83,-20.85 -390.32,-20.85 -350.56,-20.84 -332.37,-39.02 -196.01,-39.02 -163.94,-71.09 -163.94,-91.13 v1@-114.31,-140.75
SCK: DR3.2 DU1.J3 U1.J1 | length 931.6
  TOP w3.8: v1(-789.01,-288.02) -780.51,-279.52 -701.3,-279.52 -688.8,-267.02 DU1.J3@-674.99,-267.02 ; v1(-216.68,-191.93) U1.J1@-203.88,-204.73
  BOTTOM w3.8: v1(-789.01,-288.02) -780.51,-279.52 -768.51,-279.52 -753.96,-264.98 -748.73,-264.98 -733.89,-279.82 -672.94,-279.82 -665.73,-287.02 -576.7,-287.02 -556.51,-266.83 -556.51,-197.39 -553.64,-194.52 -544.18,-194.52 -541.51,-197.2 -541.51,-267.2 -524.18,-284.52 -459.3,-284.52 -454.3,-289.52 -431.51,-289.52 -420.51,-278.53 -362.08,-278.53 -350.58,-267.02 -348.07,-267.02 -342.9,-267.02 ; -342.89,-267.02 -324.01,-267.02 -315.52,-258.54 -311.86,-254.88 -300.88,-243.89 -285.61,-228.63 -253.37,-228.63 v1(-216.68,-191.93)
SCKB: DR3.1 DU1.J2 U1.J2 | length 921.8
  TOP w3.8: v1(-789.01,-267.02) DU1.J2@-706.49,-267.02
  TOP w4: v1(-191.93,-191.93) U1.J2@-179.14,-204.73
  BOTTOM w3.8: v1(-789.01,-267.02) -773.69,-267.02 -759.14,-252.48 -743.55,-252.48 -728.71,-267.32 -667.76,-267.32 -660.55,-274.52 -581.88,-274.52 -569.01,-261.65 -569.01,-192.22 -558.81,-182.02 -539.01,-182.02 -529.01,-192.02 -529.01,-262.02 -519.01,-272.02 -454.12,-272.02 -449.12,-277.02 -436.68,-277.02 -426.78,-267.12 -368.36,-267.12 -355.76,-254.52 -353.25,-254.52 -337.72,-254.52 -329.19,-254.52 -306.06,-231.39 -290.79,-216.13 -258.55,-216.13 -251.73,-209.31 -234.63,-192.21 -230.58,-188.16 -230.58,-186.17 -221.43,-177.02 -205.99,-177.02 v1@-191.09,-191.93
SCKE0: DU1.K3 U1.J4 | length 888.2
  TOP w4: DU1.K3@-674.99,-292.61 -663.17,-292.61 -651.26,-280.71 -570.32,-280.71 -551.08,-299.95 -551.08,-320.1 -559.01,-328.02 v1(-559.01,-342.02) ; U1.J4@-127.95,-204.73 v1(-115.15,-191.93)
  BOTTOM w4: v1(-559.01,-342.02) -541.51,-359.52 -541.51,-397.56 -488.47,-450.6 -404.01,-450.6 -390.08,-464.53 -370.58,-464.53 -342.12,-436.07 -292.99,-436.07 -269,-412.07 -269,-402.14 -269.01,-362.02 -204.97,-297.99 -204.97,-250.23 -184.53,-229.79 -160.58,-205.83 -146.68,-191.93 v1@-114.31,-191.93
SCKE1: DU1.K4 U1.J5 | length 982.1
  TOP w4: v1@-689.42,-305.41 -656.29,-305.41 DU1.K4@-643.49,-292.61 ; v1(-115.15,-217.52) U1.J5@-102.36,-204.73
  BOTTOM w4: v1@-689.01,-307.02 -694.01,-307.02 -709.01,-322.02 -709.01,-337.02 -703.5,-342.53 -674.51,-342.53 -647.51,-315.53 -625.5,-315.53 -609.01,-332.02 -594.01,-332.02 -553.51,-372.52 -553.51,-402.53 -493.43,-462.6 -407.51,-462.6 -395.08,-475.03 -360.08,-475.03 -333.12,-448.07 -288.02,-448.07 -257,-417.04 -257,-397.17 -257.01,-370.02 -196.97,-309.99 -196.97,-254.09 -144.9,-202.02 -129.81,-202.02 v1@-114.31,-217.52
  other v1: -689.42,-305.9
SCS0: DU1.L3 U1.K2 | length 793.7
  TOP w4: v1@-688.3,-330.73 -687.51,-330.73 DU1.L3@-674.99,-318.2 ; v1(-191.93,-217.52) U1.K2@-179.14,-230.32
  BOTTOM w4: v1@-690.99,-328.27 -690.88,-328.16 -689.88,-327.16 -677.71,-327.16 -655.58,-305.02 -619.03,-305.02 -604.03,-320.02 -561.01,-320.02 -529.51,-351.52 -529.51,-392.59 -484.5,-437.6 -421.15,-437.6 -384.58,-401.03 -366.58,-401.03 -343.54,-424.07 -297.96,-424.07 -281.01,-407.11 -281.01,-356 -222,-296.99 -213.97,-288.95 -213.97,-240.41 v1@-191.09,-217.52
  other v1: -689.3,-327.73
SCS1: DU1.L4 U1.K4 | length 873.8
  TOP w4: DU1.L4@-643.49,-318.2 v1(-630.7,-331) ; v1(-140.74,-217.52) U1.K4@-127.95,-230.32
  BOTTOM w4: v1(-630.7,-331) -609.01,-352.69 -609.01,-367.02 -604.01,-372.02 -589.01,-372.02 -565.51,-395.52 -565.51,-407.5 -502.28,-470.72 -498.48,-474.53 -411.08,-474.53 -378.58,-507.02 -270.98,-507.02 -230.98,-467.02 -188.01,-467.02 -169.01,-448.02 -169.01,-354.51 -186.97,-336.54 -186.97,-336.49 -188.97,-334.49 -188.97,-259.63 -146.87,-217.52 v1@-139.9,-217.52
SDC0-CLK: D18.1 J8.5 R125.2 | length 1163.8
  TOP w5: D18.1@-957.82,-388.31 v1@-934.35,-388.31
  SIN04 w4: v1(-934.27,-388.39) -907,-415.66 -907,-512 -815,-604 -619.86,-604 -527.86,-696 -215,-696 v1(-139.38,-620.38)
  BOTTOM w5: v1(-934.27,-388.39) -934.27,-400.86 -905.63,-429.5 J8.5@-859.74,-429.5 ; v1(-139.38,-620.38) R125.2@-108,-620.38
SDC0-CMD: D19.1 J8.3 R122.2 U1.W4 | length 1438.3
  TOP w5: R122.2@-956.27,-317.84 -956.27,-284.15 D19.1@-957.82,-282.61 v1@-934.35,-282.61 ; v1(-140,-588) -115.42,-563.42 -115.42,-473.16 U1.W4@-127.95,-460.63
  SIN04 w4: v1(-934.27,-282.69) -896,-320.96 -896,-507 -809,-594 -615.72,-594 -523.72,-686 -222,-686 -159,-623 -159,-607 v1(-140,-588)
  BOTTOM w5: v1(-934.27,-282.69) -934.27,-310.86 -902.24,-342.89 J8.3@-859.74,-342.89
SDC0-D0: D17.1 J8.7 U1.Y4 | length 1350.5
  TOP w4: v1(-140.08,-540.9) -140.08,-499.21 U1.Y4@-127.52,-486.65
  TOP w5: D17.1@-957.82,-423.54 v1@-934.35,-423.54
  SIN04 w4: v1(-934.27,-423.62) -919,-438.9 -919,-520 -825,-614 -624,-614 -532,-706 -209,-706 -141.24,-638.24 -130.24,-638.24 -117,-625 -117,-553 -129.1,-540.9 v1(-140.08,-540.9)
  BOTTOM w5: v1(-934.27,-423.62) -914.27,-443.62 -914.27,-510.86 -909.01,-516.12 J8.7@-859.74,-516.12
SDC0-D1: D16.1 J8.8 U1.Y5 | length 1500.3
  TOP w4: -106.08,-521 -106.08,-490.8 U1.Y5@-101.51,-486.23
  TOP w5: D16.1@-957.82,-458.78 v1@-934.35,-458.78 ; -106.08,-521 -106.08,-528.92 -100,-535 v1(-100,-549)
  SIN04 w4: v1(-934.27,-458.86) -934.27,-505.27 -972,-543 -972,-590 -903,-659 -751.44,-659 -725.44,-633 -649.56,-633 -535.56,-747 -205,-747 -106,-648 -106,-575 -100,-569 v1(-100,-549)
  BOTTOM w5: v1(-934.27,-458.86) -934.27,-546.99 -921.84,-559.42 J8.8@-859.74,-559.42
SDC0-D2: D15.1 J8.1 U1.Y3 | length 1410.7
  TOP w5: D15.1@-957.82,-212.14 v1@-934.35,-212.14 ; v1(-177,-617) -190,-604 -190,-583 -166.42,-559.42 -166.42,-499.96 U1.Y3@-153.11,-486.65
  SIN04 w4: v1(-934.27,-212.22) -956,-233.94 -956,-256 -947,-265 -924,-265 -885,-304 -885,-503 -803,-585 -611.99,-585 -524.99,-672 -254,-672 -199,-617 v1(-177,-617)
  BOTTOM w5: v1(-934.27,-212.22) -911.63,-234.86 -897.27,-234.86 -875.85,-256.28 J8.1@-859.74,-256.28
SDC0-D3: D20.1 J8.2 U1.AA3 | length 1299.6
  TOP w4: -156.58,-547 -156.58,-528.53 -152.69,-524.64 U1.AA3@-152.69,-511.82
  TOP w5: D20.1@-957.82,-247.37 v1@-934.35,-247.37 ; v1(-175,-591) -156.58,-572.58 -156.58,-547
  SIN04 w4: v1(-934.27,-247.45) -919.55,-247.45 -873,-294 -873,-502 -801,-574 -607.43,-574 -520.43,-661 -259,-661 -207,-609 -193,-609 v1(-175,-591)
  BOTTOM w5: v1(-934.27,-247.45) -914.27,-267.45 -914.27,-284.86 -899.55,-299.58 J8.2@-859.74,-299.58
SDC0-DET: D21.1 J8.9 R123.2 U1.AA2 | length 1320.5
  TOP w5: D21.1@-960.27,-493.86 -956.27,-497.86 R123.2@-956.27,-529.25 v1(-956.27,-555.86) ; U1.AA2@-179.14,-511.82 -179.14,-546.62 -203,-570.48 -203,-622 -152,-673 v1@-153,-673
  SIN04 w4: v1(-956.27,-555.86) -956.27,-586 -894.27,-648 -756,-648 -730,-622 -645,-622 -549,-718 -195,-718 v1(-150,-673)
  BOTTOM w5: v1(-956.27,-555.86) -956.27,-583.86 -937.4,-602.73 J8.9@-859.74,-602.73
SDQ0: DU1.P9 U1.R2 | length 340.7
  TOP w4: DU1.P9@-486.01,-394.98 v1@-474.24,-406.75 ; v1@-349.62,-383.53 -335.08,-383.53 -316.08,-364.53 -269.57,-364.53 -256.48,-351.44 -229.03,-351.44 -223.95,-346.37 -190.2,-346.37 U1.R2@-178.29,-358.27
  BOTTOM w4: v1(-473.22,-407.77) -434.76,-407.77 -421.57,-394.59 -413.62,-386.64 v1(-349.62,-386.64)
SDQ1: DU1.N9 U1.R1 | length 324.7
  TOP w4: DU1.N9@-486.01,-369.39 v1@-474.24,-381.16 ; v1(-306.51,-379.63) -267.7,-379.63 -266.09,-378.02 -251.51,-363.44 -229.03,-363.44 -223.86,-358.27 U1.R1@-203.88,-358.27
  BOTTOM w4: v1@-473.22,-382.18 -446.13,-382.18 -408.84,-344.89 -361.14,-344.89 -346.5,-359.53 -326.68,-359.53 -317.18,-369.03 -317.11,-369.03 v1(-306.51,-379.63)
  other v1: -474.22,-379.18
SDQ2: DU1.N10 U1.P2 | length 325.4
  TOP w4: DU1.N10@-454.52,-369.39 -454.52,-381.09 -453.08,-382.53 -448.8,-382.53 -441.28,-390.05 -437.56,-390.05 -430.03,-382.51 -419.01,-382.51 -413.52,-377.02 -404.01,-377.02 -398.05,-382.98 -383.58,-382.98 -380.03,-386.53 -370.08,-386.53 -355.08,-371.52 -337.08,-371.52 -318.08,-352.53 -274.54,-352.53 -261.45,-339.44 -260.38,-338.37 -180.35,-338.37 -178.29,-336.31 U1.P2@-178.29,-332.68
SDQ3: DU1.N11 U1.N3 | length 353.7
  TOP w4: DU1.N11@-423.02,-369.39 -424.14,-370.51 -436.18,-370.51 -439.01,-367.68 -439.01,-362.02 -433.87,-356.89 -419.01,-356.89 -411.44,-364.45 -406.97,-364.45 -399.04,-356.53 -386.08,-356.53 -383.58,-354.03 -368.29,-354.03 -362.79,-359.53 -339.08,-359.53 -320.08,-340.53 -279.51,-340.53 -267.89,-328.91 -192.14,-328.91 -184.01,-320.78 -154.31,-320.78 -149.11,-315.58 -149.11,-309.92 -151.94,-307.09 U1.N3@-152.7,-307.09
SDQ4: DU1.M8 U1.M1 | length 364.4
  TOP w4: DU1.M8@-517.51,-343.8 -505.74,-332.02 -503.91,-332.02 v1(-503.26,-331.37) ; v1(-278.21,-251.33) -253.01,-276.53 -208.85,-276.53 U1.M1@-203.88,-281.5
  BOTTOM w4: v1(-503.26,-331.37) -487.41,-315.53 -461.08,-315.53 -453.08,-307.53 -398.08,-307.53 -380.08,-289.53 -327.06,-289.53 -288.87,-251.33 v1(-278.21,-251.33)
SDQ5: DU1.M9 U1.M2 | length 369.9
  TOP w4: DU1.M9@-486.01,-343.8 v1@-473.22,-356.59 ; v1(-243.97,-262.02) -228.97,-262.02 -197.77,-262.02 U1.M2@-178.29,-281.5
  BOTTOM w4: v1@-473.22,-356.59 -457.08,-340.45 -457.08,-324.03 -450.58,-317.53 -388.08,-317.53 -370.58,-300.02 -322.08,-300.02 -290.58,-268.53 -265.08,-268.53 -258.57,-262.02 v1(-243.97,-262.02)
  other v1: -473.22,-354.59
SDQ6: DU1.M10 U1.M3 | length 342.9
  TOP w4: DU1.M10@-454.52,-343.8 -442.75,-332.02 v1(-439.01,-332.02) ; v1(-284.28,-283.44) -269.28,-283.44 -264.7,-288.02 -218.01,-288.02 -210.84,-295.18 -166.38,-295.18 U1.M3@-152.7,-281.5
  BOTTOM w4: v1(-439.01,-332.02) -371.44,-332.02 -368.94,-334.53 -356.58,-334.53 -334.08,-312.02 -306.89,-312.02 -294.89,-300.02 -294.89,-294.04 v1(-284.28,-283.44)
SDQ7: DU1.M11 U1.L2 | length 301.8
  TOP w4: DU1.M11@-423.02,-343.8 -410.75,-331.53 -374.58,-331.53 -372.58,-333.53 -355.51,-333.53 -349.01,-327.02 v1(-329.01,-327.02) ; v1(-229.01,-247.02) -200.08,-247.02 -191.2,-255.91 U1.L2@-178.29,-255.91
  BOTTOM w4: v1(-329.01,-327.02) -289.09,-327.02 -229.01,-266.94 v1(-229.01,-247.02)
SDQ8: DU1.R9 U1.Y1 | length 625.8
  TOP w4: DU1.R9@-486.01,-420.57 -498.02,-408.57 -523.08,-408.57 -553.5,-438.98 -553.5,-529.5 -488.67,-594.33 -481.65,-601.35 -329.25,-601.35 ; -329.25,-601.35 -319.31,-601.35 -309.37,-601.36 -279.54,-601.36 -222,-543.82 -219.34,-541.16 -219.34,-501.69 U1.Y1@-203.88,-486.23
SDQ9: DU1.R8 U1.W2 | length 584.7
  TOP w4: DU1.R8@-517.51,-420.57 -541.5,-444.56 -541.5,-524.53 -476.68,-589.35 -324.28,-589.35 -314.34,-589.35 -304.4,-589.36 ; -304.4,-589.36 -284.51,-589.36 -228.51,-533.35 -228.51,-486.52 -214.52,-472.54 -190.2,-472.54 U1.W2@-178.29,-460.63
SDQ10: DU1.T8 U1.W1 | length 531.6
  TOP w4: DU1.T8@-517.51,-446.16 -531.42,-460.07 -531.42,-498.55 -501.76,-528.21 -501.76,-533.87 -505.65,-537.75 -505.65,-543.41 -499.99,-549.07 -494.33,-549.07 -490.45,-545.18 -484.79,-545.18 -479.13,-550.84 -479.13,-556.49 -483.02,-560.38 -483.02,-566.04 -477.36,-571.69 -471.71,-571.69 -467.82,-567.81 -462.17,-567.81 -452.62,-577.35 -319.31,-577.35 -309.37,-577.35 -299.42,-577.36 -289.49,-577.36 -261.59,-549.47 -240.51,-528.38 -240.51,-478.52 -224.89,-462.9 -207,-462.9 U1.W1@-204.73,-460.63 ; U1.W1@-204.8,-461.55 U1.W1@-203.88,-460.63
SDQ11: DU1.T9 U1.V3 | length 576
  TOP w4: DU1.T9@-486.01,-446.16 -484.01,-444.15 -484.01,-437.02 -487.33,-433.7 -495.68,-433.7 -504.01,-442.02 -504.01,-464.03 -499.08,-468.96 -499.08,-513.92 -454.68,-558.32 -447.65,-565.35 -314.33,-565.35 -304.4,-565.35 -294.46,-565.36 -266.56,-537.47 -252.51,-523.41 -252.51,-462.45 -213.19,-423.14 -164.61,-423.14 U1.V3@-152.7,-435.04
SDQ12: DU1.R10 U1.U2 | length 521.7
  TOP w4: DU1.R10@-454.52,-420.57 -463.06,-420.57 -469,-426.51 -469,-498.23 -476.01,-505.24 -476.01,-520.02 -463.87,-532.16 -456.84,-532.16 -449.04,-539.96 -449.04,-546.99 -442.68,-553.35 -309.36,-553.35 -299.42,-553.35 -271.53,-525.47 -264.51,-518.44 -264.51,-461.86 -227.12,-424.48 -217.78,-415.14 -183.98,-415.14 U1.U2@-178.29,-409.45
SDQ13: DU1.T10 U1.T3 | length 542.4
  TOP w4: DU1.T10@-454.52,-446.16 -454.52,-454.77 -439.01,-470.29 -439.01,-497.02 -446.12,-504.14 -456.13,-504.14 -459.01,-507.02 -459.01,-513.02 -455.01,-517.02 -439.01,-517.02 -434.01,-522.02 -434.01,-537.02 -429.68,-541.35 -304.39,-541.35 -276.51,-513.47 -276.51,-456.44 -227.09,-407.02 -198.89,-407.02 -195.64,-403.77 -188.52,-396.66 -174.01,-396.66 -169.37,-392.02 -164.01,-392.02 -158.84,-397.19 -145.17,-397.19 -142.34,-394.36 -142.34,-386.69 -145.17,-383.86 -147.97,-383.86 U1.T3@-152.7,-383.86
SDQ14: DU1.T11 U1.T2 | length 533.1
  TOP w4: DU1.T11@-423.02,-446.16 -433.14,-446.16 -437.15,-450.17 -437.15,-455.17 -434.35,-457.97 -414.95,-457.97 -409.01,-463.92 -409.01,-483.39 -405.01,-487.39 -398.01,-487.39 -394.01,-491.39 -394.01,-499.39 -398.01,-503.39 -415.37,-503.39 -419.01,-507.02 -419.01,-523.02 -412.68,-529.35 -399.01,-529.35 -394.2,-524.55 -386.48,-524.55 -381.68,-529.35 -354.01,-529.35 -349.01,-524.35 -349.01,-507.02 -346.01,-504.02 -340.01,-504.02 -336.01,-508.02 -336.01,-525.02 -332.01,-529.02 -318.98,-529.02 -309.04,-529.03 -288.51,-508.5 -288.51,-436.52 -273.01,-421.03 -261.04,-421.03 -258.06,-421.02 -235.06,-398.02 -201.2,-398.02 -187.04,-383.86 U1.T2@-178.29,-383.86
SDQ15: DU1.R11 U1.T1 | length 533.2
  TOP w4: DU1.R11@-423.02,-420.57 -437.55,-420.57 -441.18,-424.2 -441.18,-429.85 -436.87,-434.16 -418.05,-434.16 -417.1,-435.11 ; -417.1,-435.11 -407.42,-444.78 -407.42,-447.9 -397.17,-458.16 -387.84,-458.16 -379.01,-466.99 -379.01,-512.35 -374.01,-517.35 -364.33,-517.35 -361.51,-514.52 -361.51,-491.02 -357.51,-487.02 -349.51,-487.02 -344.51,-492.02 -329.01,-492.02 -324.01,-497.02 -324.01,-512.02 -319.01,-517.02 -314.01,-517.02 -298.08,-501.1 -298.08,-437.95 -304.5,-431.53 -322.08,-431.53 -329.01,-424.6 -329.01,-417.02 -326.51,-414.53 -286.51,-414.53 -281.01,-409.02 -263.03,-409.02 -241.45,-387.44 -229.03,-387.44 -225.45,-383.86 -209.97,-383.86 U1.T1@-203.88,-383.86
SDQ16: DU1.F8 U1.E2 | length 419.9
  TOP w4: DU1.F8@-517.51,-190.25 v1(-504.71,-203.05) ; v1@-218.66,-143.33 -216.85,-141.53 -198.08,-141.53 -191.42,-134.87 -191.42,-115.5 U1.E2@-178.29,-102.37
  BOTTOM w4: v1(-504.71,-203.05) -471.56,-203.05 -458.47,-216.14 -405.47,-216.14 -391.58,-230.03 -349.98,-230.03 -334.73,-214.77 -266.98,-147.02 -229.01,-147.02 -226.01,-144.02 -221.01,-144.02 -220.31,-143.33 v1@-218.66,-143.33
  other v1: -219.42,-142.9
SDQ17: DU1.F9 U1.D2 | length 405.5
  TOP w4: v1(-499.66,-177.45) DU1.F9@-486.86,-190.25 ; v1(-224.01,-123.02) -213.4,-112.42 -213.4,-111.88 U1.D2@-178.29,-76.78
  BOTTOM w4: v1@-498.81,-177.46 -484.74,-191.53 -466.47,-191.53 -453.98,-204.02 -388.08,-204.02 -384.08,-200.03 -365.08,-200.03 -361.58,-203.53 -340.51,-203.53 -270.44,-133.45 -234.44,-133.45 v1(-224.01,-123.02)
SDQ18: DU1.E9 U1.D1 | length 344.2
  TOP w4: DU1.E9@-486.01,-164.66 -474.77,-175.91 v1(-469.97,-175.91) ; v1(-224.01,-102.02) -213.4,-91.42 -213.4,-86.29 U1.D1@-203.88,-76.78
  BOTTOM w4: v1(-469.97,-175.91) -453.86,-192.02 -369.08,-192.02 -340.83,-163.77 -320.76,-163.77 -269.44,-112.45 -234.44,-112.45 v1(-224.01,-102.02)
SDQ19: DU1.F10 U1.D3 | length 422.3
  TOP w4: DU1.F10@-454.52,-190.25 v1(-441.72,-177.46) ; v1(-321.48,-138.67) -289.59,-138.67 -267.08,-116.16 -267.08,-67.1 -239.26,-39.28 -173.36,-39.28 -152.7,-59.94 U1.D3@-152.7,-76.78
  BOTTOM w4: v1(-441.72,-177.46) -437.15,-182.03 -411.58,-182.03 -382.58,-153.03 -355.01,-153.03 -340.65,-138.67 v1(-321.48,-138.67)
SDQ20: DU1.F11 U1.A2 | length 415
  TOP w3.8: -386.08,-177.53 -381.58,-182.03 -367.58,-182.03 -363.08,-177.53
  TOP w4: DU1.F11@-423.02,-190.25 -410.3,-177.53 -386.08,-177.53 ; -363.08,-177.53 -342.08,-156.53 -342.08,-138.68 -309.08,-105.68 -309.08,-57.1 -261.33,-9.35 -261.33,-7.02 -254.66,-0.36 -249.01,-0.36 -247.77,-1.59 -241.95,-1.59 -236.38,3.98 -236.38,9.64 -237.69,10.95 -237.69,16.61 -231.33,22.98 -221.36,22.98 -217.36,18.98 -217.36,17 -213.36,13 -205.36,13 -201.36,17 -201.36,18.98 -197.36,22.98 -188.36,22.98 -178.29,12.9 -178.29,7.09 U1.A2@-178.29,0
SDQ21: DU1.D9 U1.B2 | length 401.9
  TOP w4: DU1.D9@-486.01,-139.07 v1(-473.22,-126.28) ; v1(-294.01,-107.02) -294.01,-60.08 -247.95,-14.02 -209.15,-14.02 -207.98,-12.86 -199.78,-12.86 -198.61,-14.02 -189.86,-14.02 U1.B2@-178.29,-25.59
  BOTTOM w4: v1(-473.22,-126.28) -417.23,-126.28 -386.98,-96.03 -360.58,-96.03 -349.58,-107.02 v1(-294.01,-107.02)
SDQ22: DU1.E10 U1.B1 | length 364.5
  TOP w4: v1(-468.16,-151.86) DU1.E10@-455.36,-164.66 ; v1(-305.65,-124.5) -291.05,-124.5 -279.08,-112.53 -279.08,-62.13 -242.98,-26.02 -229.03,-26.02 -228.6,-25.59 U1.B1@-203.88,-25.59
  BOTTOM w4: v1@-467.31,-151.87 -444.01,-151.87 -431.71,-139.57 -413.55,-139.57 -398.51,-124.53 -342.58,-124.53 -341.58,-123.52 -306.08,-123.52 -305.65,-123.95 v1(-305.65,-124.5)
SDQ23: DU1.E11 U1.A3 | length 447.3
  TOP w4: DU1.E11@-423.02,-164.66 -410.12,-164.66 -396.98,-151.53 -386.08,-151.53 -384.58,-153.03 -367.01,-153.03 -356.58,-142.6 -356.58,-136.21 -320.01,-99.64 -320.01,-51.05 -274.01,-5.05 -274.01,24.55 -248.58,49.98 -174.41,49.98 -152.7,28.26 -152.7,7.09 U1.A3@-152.7,0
